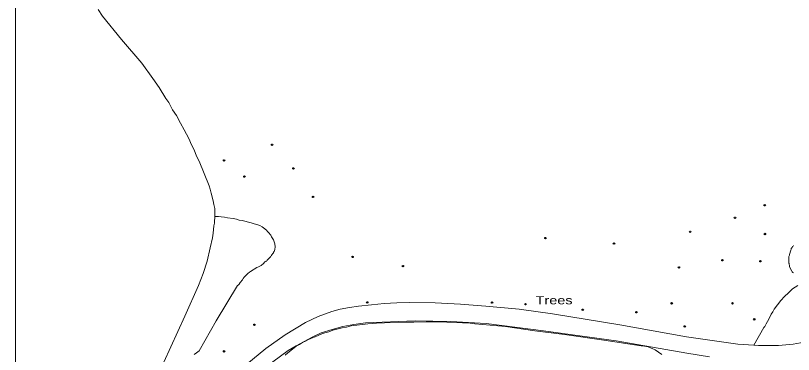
# Model space of a CAD drawing. Extents: x 528790 to 529292, y 179350 to 179856.
# Drawn here: x 528790.2 to 528960.3, y 179484.9 to 179559 of the extents above; entities that cross this region are included whole.
import ezdxf

# ---------------------------------------------------------------- set-up
doc = ezdxf.new("R2010")
doc.units = 0
doc.header["$LTSCALE"] = 0.6
doc.header["$PDMODE"] = 32
doc.header["$PDSIZE"] = 0.3
for name, color, linetype, lineweight in [('1', 7, 'Continuous', 13), ('2', 7, 'Continuous', 13), ('7', 7, 'Continuous', 13)]:
    doc.layers.add(name, color=color, linetype=linetype, lineweight=lineweight)
doc.layers.add('3', color=7, linetype='Continuous')
doc.layers.add('5', color=7, linetype='Continuous')

msp = doc.modelspace()

# ---------------------------------------------------------------- linework, layer by layer
at = {"layer": '1'}
for points in [[(528790.22, 179579.72), (528790.22, 179478.28)], [(528822.65, 179483.25), (528827.2, 179493.3), (528830.2, 179500), (528831.2, 179502.6), (528832.1, 179505.3), (528832.8, 179508.2), (528833.3, 179510.4), (528833.4, 179511.4), (528833.6, 179513.05), (528833.7, 179513.6), (528833.7, 179514.2), (528833.75, 179514.7), (528833.75, 179515.05), (528833.75, 179516.8), (528833.55, 179517.7), (528833.4, 179518.5), (528833, 179520.15), (528832.75, 179521.05), (528832.55, 179521.75), (528830.35, 179527.15), (528829.8, 179528.3), (528829.3, 179529.65), (528828.7, 179530.75), (528828.1, 179532.1), (528827.6, 179533.1), (528827.1, 179534.05), (528826.3, 179535.5), (528825.4, 179537.15), (528824.55, 179538.4), (528823.75, 179540), (528823.1, 179540.9), (528821.6, 179543.3), (528820.2, 179545.25), (528817.8, 179548.6), (528813.4, 179553.75), (528809.2, 179558.9), (528808.3, 179560.3)], [(528808.3, 179560.3), (528809.2, 179558.9), (528813.4, 179553.75), (528817.8, 179548.6), (528820.2, 179545.25), (528821.6, 179543.3), (528823.1, 179540.9), (528823.75, 179540), (528824.55, 179538.4), (528825.4, 179537.15), (528826.3, 179535.5), (528827.1, 179534.05), (528827.6, 179533.1), (528828.1, 179532.1), (528828.7, 179530.75), (528829.3, 179529.65), (528829.8, 179528.3), (528830.35, 179527.15), (528832.55, 179521.75), (528832.75, 179521.05), (528833, 179520.15), (528833.4, 179518.5), (528833.55, 179517.7), (528833.75, 179516.8), (528833.75, 179515.05), (528834.6, 179515.05), (528835.2, 179515), (528835.9, 179514.9), (528836.55, 179514.8), (528837.8, 179514.65), (528838.5, 179514.5), (528839.1, 179514.3), (528839.75, 179514.2), (528841.75, 179513.7), (528842.35, 179513.5), (528843, 179513.3), (528843.6, 179513.1), (528844.15, 179512.8), (528844.7, 179512.4), (528845.15, 179512), (528845.2, 179511.9), (528845.4, 179511.75), (528845.55, 179511.6), (528846, 179511), (528846.2, 179510.6), (528846.5, 179510.2), (528846.6, 179510), (528846.7, 179509.75), (528846.75, 179509.55), (528846.8, 179509.3), (528846.9, 179509.1), (528846.9, 179508.9), (528846.95, 179508.65), (528846.95, 179508.2), (528846.9, 179508.05), (528846.9, 179507.9), (528846.75, 179507.4), (528846.6, 179507.3), (528846.6, 179507.15), (528846.55, 179507.05), (528846.4, 179506.9), (528846.35, 179506.75), (528846.2, 179506.65), (528846.15, 179506.5), (528846, 179506.4), (528845.95, 179506.25), (528845.8, 179506.15), (528845.5, 179505.8), (528845.35, 179505.7), (528845.2, 179505.55), (528845.15, 179505.4), (528845, 179505.3), (528844.9, 179505.25), (528844.75, 179505.15), (528844.4, 179504.8), (528843.9, 179504.4), (528843.3, 179504.1), (528843, 179503.9), (528842.4, 179503.6), (528842.15, 179503.4), (528841.55, 179503.05), (528841.35, 179502.9), (528841, 179502.65), (528840.2, 179501.8)], [(528829.3, 179484.9), (528829.8, 179485.3), (528830.1, 179485.5), (528830.35, 179485.7), (528834.1, 179492.25), (528838.75, 179500), (528838.9, 179500.05), (528839.1, 179500.3), (528839.3, 179500.65), (528839.8, 179501.25), (528840, 179501.55), (528840.2, 179501.8), (528841, 179502.65), (528841.35, 179502.9), (528841.55, 179503.05), (528842.15, 179503.4), (528842.4, 179503.6), (528843, 179503.9), (528843.3, 179504.1), (528843.9, 179504.4), (528844.4, 179504.8), (528844.75, 179505.15), (528844.9, 179505.25), (528845, 179505.3), (528845.15, 179505.4), (528845.2, 179505.55), (528845.35, 179505.7), (528845.5, 179505.8), (528845.8, 179506.15), (528845.95, 179506.25), (528846, 179506.4), (528846.15, 179506.5), (528846.2, 179506.65), (528846.35, 179506.75), (528846.4, 179506.9), (528846.55, 179507.05), (528846.6, 179507.15), (528846.6, 179507.3), (528846.75, 179507.4), (528846.9, 179507.9), (528846.9, 179508.05), (528846.95, 179508.2), (528846.95, 179508.65), (528846.9, 179508.9), (528846.9, 179509.1), (528846.8, 179509.3), (528846.75, 179509.55), (528846.7, 179509.75), (528846.6, 179510), (528846.5, 179510.2), (528846.2, 179510.6), (528846, 179511), (528845.55, 179511.6), (528845.4, 179511.75), (528845.2, 179511.9), (528845.15, 179512), (528844.7, 179512.4), (528844.15, 179512.8), (528843.6, 179513.1), (528843, 179513.3), (528842.35, 179513.5), (528841.75, 179513.7), (528839.75, 179514.2), (528839.1, 179514.3), (528838.5, 179514.5), (528837.8, 179514.65), (528836.55, 179514.8), (528835.9, 179514.9), (528835.2, 179515), (528834.6, 179515.05), (528833.75, 179515.05), (528833.75, 179514.7), (528833.7, 179514.2), (528833.7, 179513.6), (528833.6, 179513.05), (528833.4, 179511.4), (528833.3, 179510.4), (528832.8, 179508.2), (528832.1, 179505.3), (528831.2, 179502.6), (528830.2, 179500), (528827.2, 179493.3), (528822.65, 179483.25)], [(528960.3, 179508.75), (528960.2, 179508.6), (528960.05, 179508.5), (528960, 179508.3), (528959.95, 179508.2), (528959.8, 179508.05), (528959.8, 179507.9), (528959.7, 179507.75), (528959.4, 179506.8), (528959.4, 179506.65), (528959.35, 179506.5), (528959.3, 179506.3), (528959.3, 179504.9), (528959.35, 179504.8), (528959.35, 179504.65), (528959.4, 179504.4), (528959.4, 179504.15), (528959.6, 179503.65), (528959.9, 179503.15), (528960, 179503), (528960.15, 179502.8), (528960.3, 179502.75)], [(528960.3, 179502.75), (528960.15, 179502.8), (528960, 179503), (528959.9, 179503.15), (528959.6, 179503.65), (528959.4, 179504.15), (528959.4, 179504.4), (528959.35, 179504.65), (528959.35, 179504.8), (528959.3, 179504.9), (528959.3, 179506.3), (528959.35, 179506.5), (528959.4, 179506.65), (528959.4, 179506.8), (528959.7, 179507.75), (528959.8, 179507.9), (528959.8, 179508.05), (528959.95, 179508.2), (528960, 179508.3), (528960.05, 179508.5), (528960.2, 179508.6), (528960.3, 179508.75)], [(528840.2, 179501.8), (528840, 179501.55), (528839.8, 179501.25), (528839.3, 179500.65), (528839.1, 179500.3), (528838.9, 179500.05), (528838.75, 179500), (528834.1, 179492.25), (528830.35, 179485.7), (528830.1, 179485.5), (528829.8, 179485.3), (528829.3, 179484.9)], [(528834.6, 179477.7), (528844.9, 179486.2), (528849.15, 179489.2), (528853.6, 179491.9), (528856.4, 179493.2), (528859.35, 179494.3), (528861.2, 179494.8), (528863.2, 179495.2), (528865.2, 179495.5), (528868, 179495.8), (528870.8, 179496.05), (528873.6, 179496.2), (528876.4, 179496.25), (528881.95, 179496.2), (528887.5, 179495.9), (528893, 179495.5), (528900.35, 179494.8), (528907.6, 179493.8), (528922.3, 179491.4), (528936.9, 179488.8), (528948.15, 179487.2), (528951.65, 179486.95), (528953.8, 179490.8), (528954, 179491.05), (528954.3, 179491.6), (528954.6, 179492.1), (528954.9, 179492.65), (528955.4, 179493.75), (528955.8, 179494.25), (528956.05, 179494.8), (528956.8, 179495.8), (528957.5, 179496.7), (528958.3, 179497.6), (528959.2, 179498.4), (528960.05, 179499.25), (528961.2, 179500)], [(528961.2, 179500), (528960.05, 179499.25), (528959.2, 179498.4), (528958.3, 179497.6), (528957.5, 179496.7), (528956.8, 179495.8), (528956.05, 179494.8), (528955.8, 179494.25), (528955.4, 179493.75), (528954.9, 179492.65), (528954.6, 179492.1), (528954.3, 179491.6), (528954, 179491.05), (528953.8, 179490.8), (528951.65, 179486.95), (528952.6, 179486.9), (528957, 179486.9), (528960.2, 179487.2), (528963.4, 179487.75)], [(528963.4, 179487.75), (528960.2, 179487.2), (528957, 179486.9), (528952.6, 179486.9), (528951.65, 179486.95), (528948.15, 179487.2), (528936.9, 179488.8), (528922.3, 179491.4), (528907.6, 179493.8), (528900.35, 179494.8), (528893, 179495.5), (528887.5, 179495.9), (528881.95, 179496.2), (528876.4, 179496.25), (528873.6, 179496.2), (528870.8, 179496.05), (528868, 179495.8), (528865.2, 179495.5), (528863.2, 179495.2), (528861.2, 179494.8), (528859.35, 179494.3), (528856.4, 179493.2), (528853.6, 179491.9), (528849.15, 179489.2), (528844.9, 179486.2), (528834.6, 179477.7)], [(528941.95, 179484.4), (528937, 179485.2), (528921.5, 179487.9), (528905.6, 179490.1), (528893.1, 179491.7), (528885.35, 179492.15), (528877.6, 179492.25), (528866.7, 179491.8), (528864.2, 179491.5), (528861.8, 179491.05), (528859.4, 179490.4), (528857, 179489.65), (528855.2, 179488.8), (528851.6, 179486.8), (528849.8, 179485.75), (528844.8, 179482.05)], [(528844.8, 179482.05), (528849.8, 179485.75), (528851.6, 179486.8), (528855.2, 179488.8), (528857, 179489.65), (528859.4, 179490.4), (528861.8, 179491.05), (528864.2, 179491.5), (528866.7, 179491.8), (528877.6, 179492.25), (528885.35, 179492.15), (528893.1, 179491.7), (528905.6, 179490.1), (528921.5, 179487.9), (528937, 179485.2), (528941.95, 179484.4)], [(528931.5, 179484.9), (528930.05, 179485.9), (528929.4, 179486.25), (528929.2, 179486.3), (528929, 179486.4), (528928.5, 179486.6), (528927.75, 179486.75), (528927.2, 179486.8), (528927, 179486.8), (528918.8, 179488.05), (528910.2, 179489.25), (528903.75, 179490.1), (528897.35, 179491), (528894, 179491.3), (528890.6, 179491.65), (528889.6, 179491.75), (528882.8, 179492.05), (528880, 179492.05), (528877.3, 179492), (528875.75, 179492), (528870.9, 179491.8), (528869.1, 179491.75), (528867.2, 179491.6), (528865.4, 179491.4), (528863.6, 179491.15), (528862.6, 179490.9), (528861.6, 179490.75), (528859.6, 179490.25), (528858.7, 179489.9), (528858.15, 179489.75), (528857.35, 179489.5), (528856.5, 179489.15), (528855.7, 179488.8), (528854.9, 179488.5), (528854.15, 179488.1), (528853.6, 179487.8), (528852.95, 179487.5), (528852.3, 179487.1), (528851.6, 179486.7), (528850.4, 179485.8), (528849.75, 179485.3), (528849.15, 179484.8)]]:
    msp.add_lwpolyline(points, dxfattribs=at)
at = {"layer": '2'}
for points in [[(528808.3, 179560.3), (528809.2, 179558.9), (528813.4, 179553.75), (528817.8, 179548.6), (528820.2, 179545.25), (528821.6, 179543.3), (528823.1, 179540.9), (528823.75, 179540), (528824.55, 179538.4), (528825.4, 179537.15), (528826.3, 179535.5), (528827.1, 179534.05), (528827.6, 179533.1), (528828.1, 179532.1), (528828.7, 179530.75), (528829.3, 179529.65), (528829.8, 179528.3), (528830.35, 179527.15), (528832.55, 179521.75), (528832.75, 179521.05), (528833, 179520.15), (528833.4, 179518.5), (528833.55, 179517.7), (528833.75, 179516.8), (528833.75, 179515.05)], [(528833.75, 179515.05), (528833.75, 179514.7), (528833.7, 179514.2), (528833.7, 179513.6), (528833.6, 179513.05), (528833.4, 179511.4), (528833.3, 179510.4), (528832.8, 179508.2), (528832.1, 179505.3), (528831.2, 179502.6), (528830.2, 179500), (528827.2, 179493.3), (528822.65, 179483.25)], [(528833.75, 179515.05), (528834.6, 179515.05), (528835.2, 179515), (528835.9, 179514.9), (528836.55, 179514.8), (528837.8, 179514.65), (528838.5, 179514.5), (528839.1, 179514.3), (528839.75, 179514.2), (528841.75, 179513.7), (528842.35, 179513.5), (528843, 179513.3), (528843.6, 179513.1), (528844.15, 179512.8), (528844.7, 179512.4), (528845.15, 179512), (528845.2, 179511.9), (528845.4, 179511.75), (528845.55, 179511.6), (528846, 179511), (528846.2, 179510.6), (528846.5, 179510.2), (528846.6, 179510), (528846.7, 179509.75), (528846.75, 179509.55), (528846.8, 179509.3), (528846.9, 179509.1), (528846.9, 179508.9), (528846.95, 179508.65), (528846.95, 179508.2), (528846.9, 179508.05), (528846.9, 179507.9), (528846.75, 179507.4), (528846.6, 179507.3), (528846.6, 179507.15), (528846.55, 179507.05), (528846.4, 179506.9), (528846.35, 179506.75), (528846.2, 179506.65), (528846.15, 179506.5), (528846, 179506.4), (528845.95, 179506.25), (528845.8, 179506.15), (528845.5, 179505.8), (528845.35, 179505.7), (528845.2, 179505.55), (528845.15, 179505.4), (528845, 179505.3), (528844.9, 179505.25), (528844.75, 179505.15), (528844.4, 179504.8), (528843.9, 179504.4), (528843.3, 179504.1), (528843, 179503.9), (528842.4, 179503.6), (528842.15, 179503.4), (528841.55, 179503.05), (528841.35, 179502.9), (528841, 179502.65), (528840.2, 179501.8), (528840, 179501.55), (528839.8, 179501.25), (528839.3, 179500.65), (528839.1, 179500.3), (528838.9, 179500.05), (528838.75, 179500), (528834.1, 179492.25), (528830.35, 179485.7), (528830.1, 179485.5), (528829.8, 179485.3), (528829.3, 179484.9)], [(528960.3, 179508.75), (528960.2, 179508.6), (528960.05, 179508.5), (528960, 179508.3), (528959.95, 179508.2), (528959.8, 179508.05), (528959.8, 179507.9), (528959.7, 179507.75), (528959.4, 179506.8), (528959.4, 179506.65), (528959.35, 179506.5), (528959.3, 179506.3), (528959.3, 179504.9), (528959.35, 179504.8), (528959.35, 179504.65), (528959.4, 179504.4), (528959.4, 179504.15), (528959.6, 179503.65), (528959.9, 179503.15), (528960, 179503), (528960.15, 179502.8), (528960.3, 179502.75)], [(528986.2, 179507.8), (528985, 179506.05), (528981.15, 179500.9), (528980.5, 179500), (528980.55, 179499.9), (528979, 179498.15), (528977.4, 179496.3), (528975.8, 179494.65), (528974.8, 179493.75), (528973.8, 179492.8), (528972.8, 179491.9), (528971.75, 179491.1), (528970.6, 179490.3), (528969.4, 179489.65), (528967.5, 179488.8), (528965.5, 179488.25), (528963.4, 179487.75), (528960.2, 179487.2), (528957, 179486.9), (528952.6, 179486.9), (528951.65, 179486.95)], [(528961.2, 179500), (528960.05, 179499.25), (528959.2, 179498.4), (528958.3, 179497.6), (528957.5, 179496.7), (528956.8, 179495.8), (528956.05, 179494.8), (528955.8, 179494.25), (528955.4, 179493.75), (528954.9, 179492.65), (528954.6, 179492.1), (528954.3, 179491.6), (528954, 179491.05), (528953.8, 179490.8), (528951.65, 179486.95)], [(528834.6, 179477.7), (528844.9, 179486.2), (528849.15, 179489.2), (528853.6, 179491.9), (528856.4, 179493.2), (528859.35, 179494.3), (528861.2, 179494.8), (528863.2, 179495.2), (528865.2, 179495.5), (528868, 179495.8), (528870.8, 179496.05), (528873.6, 179496.2), (528876.4, 179496.25), (528881.95, 179496.2), (528887.5, 179495.9), (528893, 179495.5), (528900.35, 179494.8), (528907.6, 179493.8), (528922.3, 179491.4), (528936.9, 179488.8), (528948.15, 179487.2), (528951.65, 179486.95)], [(528844.8, 179482.05), (528849.8, 179485.75), (528851.6, 179486.8), (528855.2, 179488.8), (528857, 179489.65), (528859.4, 179490.4), (528861.8, 179491.05), (528864.2, 179491.5), (528866.7, 179491.8), (528877.6, 179492.25), (528885.35, 179492.15), (528893.1, 179491.7), (528905.6, 179490.1), (528921.5, 179487.9), (528937, 179485.2), (528941.95, 179484.4)], [(528931.5, 179484.9), (528930.05, 179485.9), (528929.4, 179486.25), (528929.2, 179486.3), (528929, 179486.4), (528928.5, 179486.6), (528927.75, 179486.75), (528927.2, 179486.8), (528927, 179486.8), (528918.8, 179488.05), (528910.2, 179489.25), (528903.75, 179490.1), (528897.35, 179491), (528894, 179491.3), (528890.6, 179491.65), (528889.6, 179491.75), (528882.8, 179492.05), (528880, 179492.05), (528877.3, 179492), (528875.75, 179492), (528870.9, 179491.8), (528869.1, 179491.75), (528867.2, 179491.6), (528865.4, 179491.4), (528863.6, 179491.15), (528862.6, 179490.9), (528861.6, 179490.75), (528859.6, 179490.25), (528858.7, 179489.9), (528858.15, 179489.75), (528857.35, 179489.5), (528856.5, 179489.15), (528855.7, 179488.8), (528854.9, 179488.5), (528854.15, 179488.1), (528853.6, 179487.8), (528852.95, 179487.5), (528852.3, 179487.1), (528851.6, 179486.7), (528850.4, 179485.8), (528849.75, 179485.3), (528849.15, 179484.8)]]:
    msp.add_lwpolyline(points, dxfattribs=at)
at = {"layer": '3'}
for p in [(528846.3, 179530.75), (528835.8, 179527.35), (528850.95, 179525.6), (528840.25, 179523.8), (528855.25, 179519.35), (528954, 179517.55), (528947.5, 179514.8), (528937.7, 179511.75), (528906.05, 179510.35), (528954.05, 179511.25), (528921.05, 179509.15), (528863.9, 179506.25), (528944.75, 179505.5), (528953.05, 179505.3), (528874.9, 179504.25), (528935.25, 179503.95), (528867.1, 179496.3), (528894.4, 179496.25), (528933.65, 179496.1), (528946.95, 179496.1), (528901.7, 179495.9), (528914.2, 179494.7), (528925.95, 179494.15), (528951.7, 179492.6), (528842.45, 179491.4), (528936.5, 179491.05), (528835.8, 179485.6)]:
    msp.add_point(p, dxfattribs=at)
at = {"layer": '7'}
msp.add_lwpolyline([(528790.22, 179356.024), (529290.22, 179356.024), (529290.22, 179856.024), (528790.22, 179856.024)], close=True, dxfattribs=at)

# ---------------------------------------------------------------- texts
at = {"layer": '5', "width": 1.35}
msp.add_text('Trees', height=1.75, dxfattribs=at).set_placement((528903.91, 179495.89))

doc.saveas('drawing.dxf')
